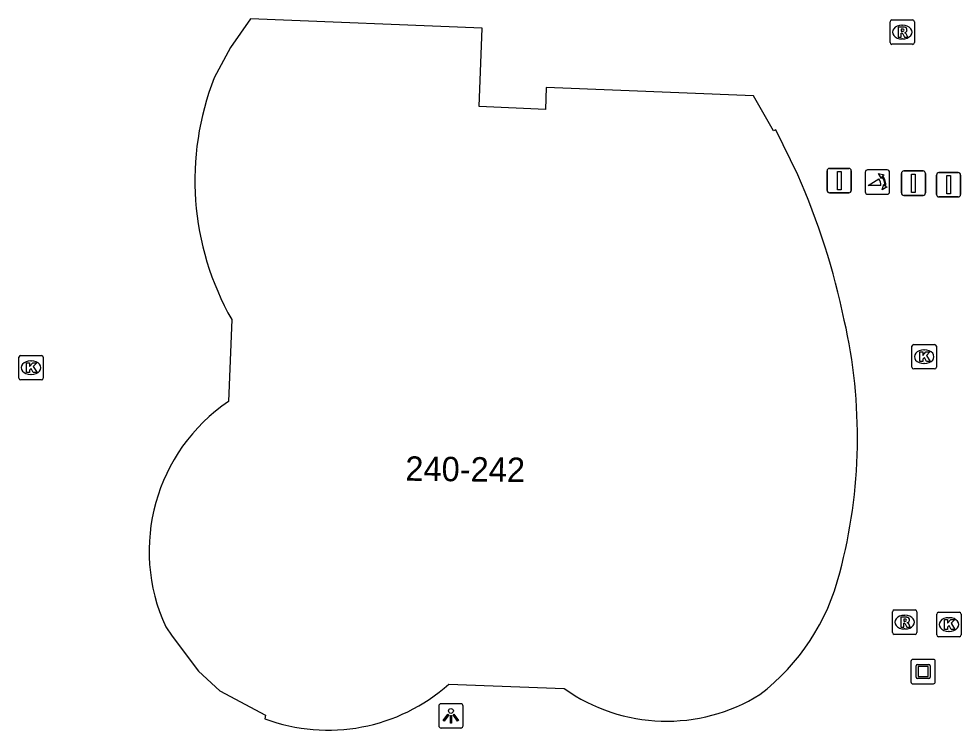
# Model space of a CAD drawing. Extents: x 160891 to 161384, y 386490 to 386907.
# Drawn here: x 161102.06 to 161140.68, y 386519.48 to 386548.63 of the extents above; entities that cross this region are included whole.
import ezdxf

# ---------------------------------------------------------------- set-up
doc = ezdxf.new("R2010")
doc.units = 0
for name, color, linetype in [('IMGEO_Afsluitpaal', 7, 'Continuous'), ('IMGEO_Kolk', 7, 'Continuous'), ('IMGEO_Kunstobject', 7, 'Continuous'), ('IMGEO_Lichtpunt', 7, 'Continuous'), ('IMGEO_Pand', 7, 'Continuous'), ('IMGEO_Pand_nummerreeks', 7, 'Continuous'), ('IMGEO_Poller', 7, 'Continuous'), ('IMGEO_Rioolput', 7, 'Continuous')]:
    doc.layers.add(name, color=color, linetype=linetype)

msp = doc.modelspace()

# ---------------------------------------------------------------- linework, layer by layer
at = {"layer": 'IMGEO_Afsluitpaal'}
for p, q in [((161135.291, 386542.505), (161136.081, 386542.505)), ((161136.081, 386542.505), (161135.291, 386542.505)), ((161135.191, 386541.605), (161135.191, 386542.405)), ((161135.191, 386542.405), (161135.191, 386541.605)), ((161136.181, 386542.405), (161136.181, 386541.605)), ((161136.181, 386541.605), (161136.181, 386542.405)), ((161138.234, 386541.499), (161138.234, 386542.299)), ((161138.234, 386542.299), (161138.234, 386541.499)), ((161138.334, 386542.399), (161139.124, 386542.399)), ((161139.124, 386542.399), (161138.334, 386542.399)), ((161139.224, 386542.299), (161139.224, 386541.499)), ((161139.224, 386541.499), (161139.224, 386542.299)), ((161139.674, 386541.434), (161139.674, 386542.234)), ((161139.674, 386542.234), (161139.674, 386541.434)), ((161139.774, 386542.334), (161140.564, 386542.334)), ((161140.564, 386542.334), (161139.774, 386542.334)), ((161140.664, 386542.234), (161140.664, 386541.434)), ((161140.664, 386541.434), (161140.664, 386542.234)), ((161136.081, 386541.505), (161135.291, 386541.505)), ((161135.291, 386541.505), (161136.081, 386541.505)), ((161139.124, 386541.399), (161138.334, 386541.399)), ((161138.334, 386541.399), (161139.124, 386541.399)), ((161140.564, 386541.334), (161139.774, 386541.334)), ((161139.774, 386541.334), (161140.564, 386541.334))]:
    msp.add_line(p, q, dxfattribs=at)
for points in [[(161135.611, 386542.38), (161135.761, 386542.38), (161135.761, 386541.63), (161135.611, 386541.63), (161135.611, 386542.38)], [(161138.654, 386542.274), (161138.804, 386542.274), (161138.804, 386541.524), (161138.654, 386541.524), (161138.654, 386542.274)], [(161140.094, 386542.209), (161140.244, 386542.209), (161140.244, 386541.459), (161140.094, 386541.459), (161140.094, 386542.209)]]:
    msp.add_lwpolyline(points, dxfattribs=at)
for centre, start, end in [((161135.291, 386542.405), 90, 180), ((161135.291, 386542.405), 90, 180), ((161136.081, 386542.405), 0, 90), ((161136.081, 386542.405), 360, 90), ((161138.334, 386542.299), 90, 180), ((161138.334, 386542.299), 90, 180), ((161139.124, 386542.299), 0, 90), ((161139.124, 386542.299), 360, 90), ((161139.774, 386542.234), 90, 180), ((161139.774, 386542.234), 90, 180), ((161140.564, 386542.234), 0, 90), ((161140.564, 386542.234), 360, 90), ((161135.291, 386541.605), 180, 270), ((161135.291, 386541.605), 180, 270), ((161136.081, 386541.605), 270, 0), ((161136.081, 386541.605), 270, 0), ((161138.334, 386541.499), 180, 270), ((161138.334, 386541.499), 180, 270), ((161139.124, 386541.499), 270, 0), ((161139.124, 386541.499), 270, 0), ((161139.774, 386541.434), 180, 270), ((161139.774, 386541.434), 180, 270), ((161140.564, 386541.434), 270, 0), ((161140.564, 386541.434), 270, 0)]:
    msp.add_arc(centre, 0.1, start, end, dxfattribs=at)
at = {"layer": 'IMGEO_Kolk'}
for p, q in [((161138.668, 386534.363), (161138.668, 386535.215)), ((161138.743, 386535.289), (161139.595, 386535.289)), ((161139.669, 386535.215), (161139.669, 386534.363)), ((161102.133, 386534.838), (161102.985, 386534.838)), ((161139.156, 386535.069), (161139.181, 386535.069)), ((161102.058, 386533.912), (161102.058, 386534.764)), ((161102.546, 386534.618), (161102.571, 386534.618)), ((161103.059, 386534.764), (161103.059, 386533.912)), ((161139.179, 386534.509), (161139.154, 386534.509)), ((161102.569, 386534.058), (161102.544, 386534.058)), ((161139.595, 386534.289), (161138.743, 386534.289)), ((161102.985, 386533.838), (161102.133, 386533.838)), ((161139.683, 386523.387), (161139.683, 386524.239)), ((161139.758, 386524.313), (161140.61, 386524.313)), ((161140.171, 386524.093), (161140.196, 386524.093)), ((161140.684, 386524.239), (161140.684, 386523.387)), ((161140.61, 386523.313), (161139.758, 386523.313)), ((161140.194, 386523.533), (161140.169, 386523.533))]:
    msp.add_line(p, q, dxfattribs=at)
for points in [[(161138.668, 386534.363), (161138.668, 386535.215)], [(161138.743, 386535.289), (161139.595, 386535.289)], [(161139.669, 386535.215), (161139.669, 386534.363)], [(161102.133, 386534.838), (161102.985, 386534.838)], [(161138.989, 386534.989), (161139.112, 386534.989), (161139.112, 386534.838), (161139.242, 386534.989), (161139.406, 386534.989), (161139.26, 386534.838), (161139.413, 386534.589), (161139.261, 386534.589), (161139.176, 386534.753), (161139.112, 386534.686), (161139.112, 386534.589), (161138.989, 386534.589), (161138.989, 386534.989)], [(161102.058, 386533.912), (161102.058, 386534.764)], [(161102.379, 386534.538), (161102.502, 386534.538), (161102.502, 386534.387), (161102.632, 386534.538), (161102.796, 386534.538), (161102.65, 386534.387), (161102.803, 386534.138), (161102.651, 386534.138), (161102.566, 386534.302), (161102.502, 386534.235), (161102.502, 386534.138), (161102.379, 386534.138), (161102.379, 386534.538)], [(161103.059, 386534.764), (161103.059, 386533.912)], [(161139.595, 386534.289), (161138.743, 386534.289)], [(161102.985, 386533.838), (161102.133, 386533.838)], [(161139.683, 386523.387), (161139.683, 386524.239)], [(161139.758, 386524.313), (161140.61, 386524.313)], [(161140.004, 386524.013), (161140.127, 386524.013), (161140.127, 386523.862), (161140.257, 386524.013), (161140.421, 386524.013), (161140.275, 386523.862), (161140.428, 386523.613), (161140.276, 386523.613), (161140.191, 386523.777), (161140.127, 386523.71), (161140.127, 386523.613), (161140.004, 386523.613), (161140.004, 386524.013)], [(161140.684, 386524.239), (161140.684, 386523.387)], [(161140.61, 386523.313), (161139.758, 386523.313)]]:
    msp.add_lwpolyline(points, dxfattribs=at)
for centre, start, end in [((161138.745, 386535.213), 91.552, 178.448), ((161138.745, 386535.213), 91.552, 178.448), ((161139.593, 386535.213), 1.552, 88.448), ((161139.593, 386535.213), 1.552, 88.448), ((161102.135, 386534.762), 91.552, 178.448), ((161102.135, 386534.762), 91.552, 178.448), ((161102.983, 386534.762), 1.552, 88.448), ((161102.983, 386534.762), 1.552, 88.448), ((161138.745, 386534.365), 181.552, 268.448), ((161138.745, 386534.365), 181.552, 268.448), ((161139.593, 386534.365), 271.552, 358.448), ((161139.593, 386534.365), 271.552, 358.448), ((161102.135, 386533.914), 181.552, 268.448), ((161102.135, 386533.914), 181.552, 268.448), ((161102.983, 386533.914), 271.552, 358.448), ((161102.983, 386533.914), 271.552, 358.448), ((161139.76, 386524.237), 91.552, 178.448), ((161139.76, 386524.237), 91.552, 178.448), ((161140.608, 386524.237), 1.552, 88.448), ((161140.608, 386524.237), 1.552, 88.448), ((161139.76, 386523.389), 181.552, 268.448), ((161139.76, 386523.389), 181.552, 268.448), ((161140.608, 386523.389), 271.552, 358.448), ((161140.608, 386523.389), 271.552, 358.448)]:
    msp.add_arc(centre, 0.0765, start, end, dxfattribs=at)
for centre, major_axis, ratio, start_param, end_param in [((161139.155, 386534.789), (-0.387, 0.002), 0.722429, 4.712389, 7.853982), ((161139.18, 386534.789), (-0.39, 0.002), 0.717154, 1.570796, 4.712389), ((161102.545, 386534.338), (-0.387, 0.002), 0.722429, 4.712389, 7.853982), ((161102.57, 386534.338), (-0.39, 0.002), 0.717154, 1.570796, 4.712389), ((161140.17, 386523.813), (-0.387, 0.002), 0.722429, 4.712389, 7.853982), ((161140.195, 386523.813), (-0.39, 0.002), 0.717154, 1.570796, 4.712389)]:
    msp.add_ellipse(centre, major_axis=major_axis, ratio=ratio, start_param=start_param, end_param=end_param, dxfattribs=at)
at = {"layer": 'IMGEO_Kunstobject'}
for p, q in [((161138.626, 386522.301), (161138.626, 386521.46)), ((161138.626, 386522.301), (161138.626, 386521.46)), ((161139.542, 386522.385), (161138.701, 386522.385)), ((161139.542, 386522.385), (161138.701, 386522.385)), ((161138.84, 386521.649), (161138.84, 386522.123)), ((161138.89, 386522.173), (161139.364, 386522.173)), ((161138.92, 386522.073), (161138.92, 386521.699)), ((161139.314, 386522.093), (161138.94, 386522.093)), ((161139.334, 386521.699), (161139.334, 386522.073)), ((161139.414, 386522.123), (161139.414, 386521.649)), ((161139.626, 386521.469), (161139.626, 386522.31)), ((161139.626, 386521.469), (161139.626, 386522.31)), ((161138.94, 386521.679), (161139.314, 386521.679)), ((161138.71, 386521.385), (161139.551, 386521.385)), ((161138.71, 386521.385), (161139.551, 386521.385)), ((161139.364, 386521.599), (161138.89, 386521.599))]:
    msp.add_line(p, q, dxfattribs=at)
for centre, radius, start, end in [((161138.704, 386522.307), 0.0779, 92.4484, 184.2845), ((161138.704, 386522.307), 0.0779, 92.4484, 184.2845), ((161138.89, 386522.123), 0.05, 90, 180), ((161138.94, 386522.073), 0.02, 90, 180), ((161139.314, 386522.073), 0.02, 360, 90), ((161139.364, 386522.123), 0.05, 360, 90), ((161139.548, 386522.307), 0.0779, 2.4484, 94.2845), ((161139.548, 386522.307), 0.0779, 2.4484, 94.2845), ((161138.89, 386521.649), 0.05, 180, 270), ((161138.94, 386521.699), 0.02, 180, 270), ((161139.314, 386521.699), 0.02, 270, 0), ((161139.364, 386521.649), 0.05, 270, 0), ((161138.704, 386521.463), 0.0779, 182.4484, 274.2845), ((161138.704, 386521.463), 0.0779, 182.4484, 274.2845), ((161139.548, 386521.463), 0.0779, 272.4484, 4.2845), ((161139.548, 386521.463), 0.0779, 272.4484, 4.2845)]:
    msp.add_arc(centre, radius, start, end, dxfattribs=at)
at = {"layer": 'IMGEO_Lichtpunt'}
for p, q in [((161120.173, 386520.569), (161119.365, 386520.569)), ((161120.173, 386520.569), (161119.365, 386520.569)), ((161119.271, 386520.474), (161119.271, 386519.667)), ((161119.271, 386520.474), (161119.271, 386519.667)), ((161120.267, 386519.667), (161120.267, 386520.474)), ((161120.267, 386519.667), (161120.267, 386520.474)), ((161119.365, 386519.573), (161120.173, 386519.573)), ((161119.365, 386519.573), (161120.173, 386519.573))]:
    msp.add_line(p, q, dxfattribs=at)
for points in [[(161119.645, 386520.138), (161119.684, 386520.11), (161119.496, 386519.848), (161119.458, 386519.875), (161119.645, 386520.138)], [(161119.857, 386520.11), (161119.895, 386520.137), (161120.082, 386519.875), (161120.043, 386519.847), (161119.857, 386520.11)], [(161119.747, 386520.09), (161119.794, 386520.09), (161119.794, 386519.768), (161119.747, 386519.768), (161119.747, 386520.09)]]:
    msp.add_lwpolyline(points, dxfattribs=at)
msp.add_circle((161119.77, 386520.272), 0.0994, dxfattribs=at)
for centre, start, end in [((161119.365, 386520.474), 90, 180), ((161119.365, 386520.474), 90, 180), ((161120.173, 386520.474), 0, 90), ((161120.173, 386520.474), 0, 90), ((161119.365, 386519.667), 180, 270), ((161119.365, 386519.667), 180, 270), ((161120.173, 386519.667), 270, 0), ((161120.173, 386519.667), 270, 360)]:
    msp.add_arc(centre, 0.0946, start, end, dxfattribs=at)
at = {"layer": 'IMGEO_Pand'}
for points in [[(161133.984, 386542.246), (161133.082, 386544.09), (161132.989, 386544.045), (161132.172, 386545.476), (161123.673, 386545.824), (161123.652, 386544.924), (161120.928, 386545.042), (161121.056, 386548.259), (161111.552, 386548.634), (161110.736, 386547.454), (161110.068, 386546.223)], [(161110.787, 386536.307), (161110.654, 386532.956)], [(161108.077, 386523.72), (161108.346, 386523.332), (161109.425, 386521.897), (161110.299, 386521.096), (161112.164, 386520.096), (161112.145, 386519.949)], [(161119.688, 386521.369), (161124.412, 386521.191)]]:
    msp.add_lwpolyline(points, dxfattribs=at)
for centre, radius, start, end in [((161120.826, 386542.019), 11.551, 158.6561, 209.6383), ((161107.732, 386530.554), 28.738, 11.4916, 24.0075), ((161114.811, 386531.479), 21.623, 345.1161, 12.8256), ((161114.811, 386526.819), 7.412, 124.1093, 204.7107), ((161126.927, 386528.129), 9.053, 307.4647, 345.9122), ((161114.735, 386526.936), 7.451, 249.6615, 311.6613), ((161128.61, 386527.104), 7.252, 234.6294, 301.8291)]:
    msp.add_arc(centre, radius, start, end, dxfattribs=at)
at = {"layer": 'IMGEO_Poller'}
for p, q in [((161136.755, 386542.347), (161136.755, 386541.54)), ((161136.755, 386542.347), (161136.755, 386541.54)), ((161137.657, 386542.442), (161136.849, 386542.442)), ((161137.657, 386542.442), (161136.849, 386542.442)), ((161137.751, 386541.54), (161137.751, 386542.347)), ((161137.751, 386541.54), (161137.751, 386542.347)), ((161136.849, 386541.445), (161137.657, 386541.445)), ((161136.849, 386541.445), (161137.657, 386541.445))]:
    msp.add_line(p, q, dxfattribs=at)
for points in [[(161137.434, 386542.171), (161137.422, 386542.098), (161137.297, 386542.303)], [(161137.297, 386542.303), (161137.528, 386542.237), (161137.457, 386542.205)], [(161137.39, 386541.798), (161136.877, 386541.798), (161137.307, 386542.073)], [(161137.45, 386541.626), (161137.516, 386541.857), (161137.546, 386541.789)], [(161137.582, 386541.762), (161137.654, 386541.751), (161137.45, 386541.626)]]:
    msp.add_lwpolyline(points, dxfattribs=at)
for centre, radius, start, end in [((161136.849, 386542.347), 0.0946, 90, 180), ((161136.849, 386542.347), 0.0946, 90, 180), ((161137.076, 386541.858), 0.476, 351.7527, 41.1691), ((161137.076, 386541.858), 0.516, 349.3569, 42.2912), ((161137.657, 386542.347), 0.0946, 0, 90), ((161137.657, 386542.347), 0.0946, 0, 90), ((161137.062, 386541.848), 0.332, 351.3247, 42.4854), ((161136.849, 386541.54), 0.0946, 180, 270), ((161136.849, 386541.54), 0.0946, 180, 270), ((161137.657, 386541.54), 0.0946, 270, 0), ((161137.657, 386541.54), 0.0946, 270, 0)]:
    msp.add_arc(centre, radius, start, end, dxfattribs=at)
at = {"layer": 'IMGEO_Rioolput'}
for p, q in [((161137.769, 386547.664), (161137.769, 386548.516)), ((161137.844, 386548.59), (161138.696, 386548.59)), ((161138.257, 386548.37), (161138.282, 386548.37)), ((161138.77, 386548.516), (161138.77, 386547.664)), ((161138.696, 386547.59), (161137.844, 386547.59)), ((161138.28, 386547.81), (161138.255, 386547.81)), ((161137.944, 386524.41), (161138.796, 386524.41)), ((161137.869, 386523.484), (161137.869, 386524.336)), ((161138.357, 386524.19), (161138.382, 386524.19)), ((161138.87, 386524.336), (161138.87, 386523.484)), ((161138.38, 386523.63), (161138.355, 386523.63)), ((161138.796, 386523.41), (161137.944, 386523.41))]:
    msp.add_line(p, q, dxfattribs=at)
for points in [[(161137.769, 386547.664), (161137.769, 386548.516)], [(161137.844, 386548.59), (161138.696, 386548.59)], [(161138.77, 386548.516), (161138.77, 386547.664)], [(161138.358, 386548.288), (161138.106, 386548.29), (161138.106, 386547.89)], [(161138.106, 386547.89), (161138.23, 386547.89), (161138.23, 386548.052), (161138.241, 386548.052)], [(161138.284, 386548.209), (161138.23, 386548.209), (161138.23, 386548.128)], [(161138.23, 386548.128), (161138.282, 386548.128)], [(161138.288, 386548.023), (161138.359, 386547.89), (161138.499, 386547.89), (161138.434, 386548.016)], [(161138.696, 386547.59), (161137.844, 386547.59)], [(161137.944, 386524.41), (161138.796, 386524.41)], [(161137.869, 386523.484), (161137.869, 386524.336)], [(161138.458, 386524.108), (161138.206, 386524.11), (161138.206, 386523.71)], [(161138.384, 386524.029), (161138.33, 386524.029), (161138.33, 386523.948)], [(161138.87, 386524.336), (161138.87, 386523.484)], [(161138.206, 386523.71), (161138.33, 386523.71), (161138.33, 386523.872), (161138.341, 386523.872)], [(161138.33, 386523.948), (161138.382, 386523.948)], [(161138.388, 386523.843), (161138.459, 386523.71), (161138.599, 386523.71), (161138.534, 386523.836)], [(161138.796, 386523.41), (161137.944, 386523.41)]]:
    msp.add_lwpolyline(points, dxfattribs=at)
for centre, radius, start, end in [((161137.846, 386548.514), 0.0765, 91.552, 178.448), ((161137.846, 386548.514), 0.0765, 91.552, 178.448), ((161138.694, 386548.514), 0.0765, 1.552, 88.448), ((161138.694, 386548.514), 0.0765, 1.552, 88.448), ((161138.24, 386547.999), 0.0533, 26.0293, 88.6989), ((161138.266, 386548.317), 0.19, 274.7715, 282.9687), ((161138.29, 386548.113), 0.0964, 77.0061, 93.1865), ((161138.304, 386548.17), 0.0378, 276.6634, 79.6772), ((161138.357, 386548.178), 0.109, 350.3612, 89.416), ((161138.355, 386548.178), 0.112, 277.5842, 350.9817), ((161138.339, 386547.963), 0.108, 29.5134, 73.7905), ((161137.846, 386547.666), 0.0765, 181.552, 268.448), ((161137.846, 386547.666), 0.0765, 181.552, 268.448), ((161138.694, 386547.666), 0.0765, 271.552, 358.448), ((161138.694, 386547.666), 0.0765, 271.552, 358.448), ((161137.946, 386524.334), 0.0765, 91.552, 178.448), ((161137.946, 386524.334), 0.0765, 91.552, 178.448), ((161138.794, 386524.334), 0.0765, 1.552, 88.448), ((161138.794, 386524.334), 0.0765, 1.552, 88.448), ((161138.39, 386523.933), 0.0964, 77.0061, 93.1865), ((161138.404, 386523.99), 0.0378, 276.6634, 79.6772), ((161138.457, 386523.998), 0.109, 350.3612, 89.416), ((161138.455, 386523.998), 0.112, 277.5842, 350.9817), ((161138.34, 386523.819), 0.0533, 26.0293, 88.6989), ((161138.366, 386524.137), 0.19, 274.7715, 282.9687), ((161138.439, 386523.783), 0.108, 29.5134, 73.7905), ((161137.946, 386523.486), 0.0765, 181.552, 268.448), ((161137.946, 386523.486), 0.0765, 181.552, 268.448), ((161138.794, 386523.486), 0.0765, 271.552, 358.448), ((161138.794, 386523.486), 0.0765, 271.552, 358.448)]:
    msp.add_arc(centre, radius, start, end, dxfattribs=at)
for centre, major_axis, ratio, start_param, end_param in [((161138.256, 386548.09), (-0.387, 0.002), 0.722429, 4.712389, 7.853982), ((161138.281, 386548.09), (-0.39, 0.002), 0.717154, 1.570796, 4.712389), ((161138.356, 386523.91), (-0.387, 0.002), 0.722429, 4.712389, 7.853982), ((161138.381, 386523.91), (-0.39, 0.002), 0.717154, 1.570796, 4.712389)]:
    msp.add_ellipse(centre, major_axis=major_axis, ratio=ratio, start_param=start_param, end_param=end_param, dxfattribs=at)

# ---------------------------------------------------------------- texts
at = {"layer": 'IMGEO_Pand_nummerreeks'}
msp.add_text('240-242', height=1, rotation=359.3504, dxfattribs=at).set_placement((161117.896, 386529.706))

doc.saveas('drawing.dxf')
